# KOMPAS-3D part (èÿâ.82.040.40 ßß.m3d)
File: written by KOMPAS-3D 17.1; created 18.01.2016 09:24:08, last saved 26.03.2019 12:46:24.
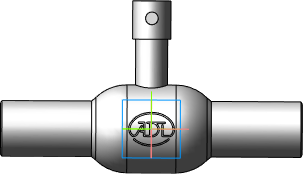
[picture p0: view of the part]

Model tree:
1. Операция без истории:5  (labels: Сталь 20  ГОСТ 1050-88)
